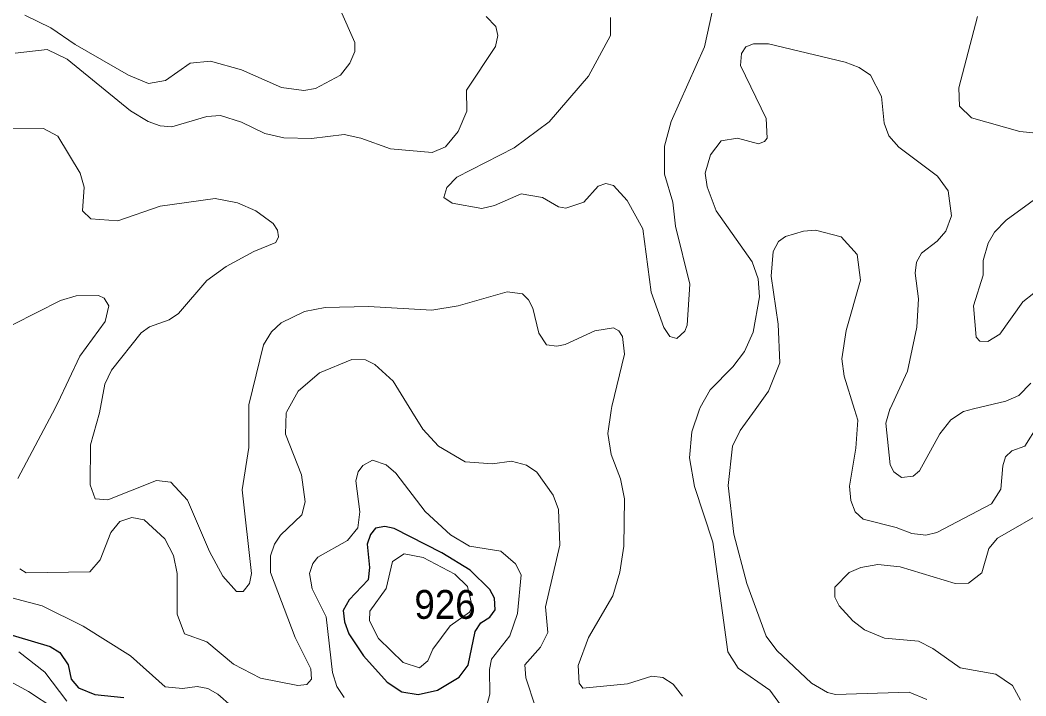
# Model space of a CAD drawing. Extents: x 473.9 to 500, y 7733.1 to 7760.8.
# Drawn here: x 486.475 to 489.264, y 7741.528 to 7743.401 of the extents above; entities that cross this region are included whole.
import ezdxf
from ezdxf.enums import TextEntityAlignment as Align

# ---------------------------------------------------------------- set-up
doc = ezdxf.new("R2010")
doc.units = 0
doc.header["$LTSCALE"] = 0.032
for name, color, linetype, lineweight in [('1', 7, 'Continuous', 25), ('2', 7, 'Continuous', 13), ('26', 7, 'Continuous', 25)]:
    doc.layers.add(name, color=color, linetype=linetype, lineweight=lineweight)
doc.layers.add('21', color=7, linetype='Continuous')

msp = doc.modelspace()

# ---------------------------------------------------------------- linework, layer by layer
at = {"layer": '1'}
msp.add_lwpolyline([(487.7365, 7741.7062), (487.7525, 7741.7297), (487.7769, 7741.7462), (487.7922, 7741.7664), (487.7906, 7741.7985), (487.7773, 7741.8222), (487.7228, 7741.8761), (487.644, 7741.9245), (487.5117, 7741.9919), (487.4865, 7741.9971), (487.4603, 7741.9926), (487.446, 7741.975), (487.4369, 7741.948), (487.4433, 7741.8837), (487.4403, 7741.8491), (487.3868, 7741.7937), (487.371, 7741.7642), (487.374, 7741.7331), (487.3859, 7741.6994), (487.4268, 7741.6389), (487.4924, 7741.5654), (487.5336, 7741.5386), (487.5787, 7741.5316), (487.6324, 7741.5437), (487.6925, 7741.5798), (487.7176, 7741.6125)], close=True, dxfattribs=at)
msp.add_lwpolyline([(486.4182, 7741.706), (486.5584, 7741.6649), (486.5849, 7741.6477), (486.6079, 7741.6135), (486.6161, 7741.5742), (486.6365, 7741.5497), (486.6823, 7741.5313), (486.7627, 7741.5227)], dxfattribs=at)
at = {"layer": '2'}
for points in [[(488.1121, 7743.4086), (488.1123, 7743.3588), (488.0507, 7743.2462), (487.9419, 7743.1195), (487.8444, 7743.0473), (487.6862, 7742.9659), (487.6579, 7742.9375), (487.6494, 7742.9097), (487.6726, 7742.8936), (487.7555, 7742.8791), (487.7899, 7742.887), (487.864, 7742.9198), (487.9233, 7742.9096), (487.9678, 7742.8834), (487.9876, 7742.8799), (488.0377, 7742.8962), (488.0775, 7742.9414), (488.0986, 7742.9481), (488.1206, 7742.9427), (488.1584, 7742.9011), (488.2018, 7742.8223), (488.225, 7742.647), (488.2598, 7742.5488), (488.2763, 7742.5239), (488.2959, 7742.5189), (488.3182, 7742.5385), (488.3244, 7742.5553), (488.3317, 7742.6689), (488.2923, 7742.8298), (488.2844, 7742.8962), (488.2618, 7742.9745), (488.2619, 7743.0517), (488.2801, 7743.1203), (488.3726, 7743.3277), (488.4002, 7743.4537)], [(487.7669, 7743.4116), (487.794, 7743.3834), (487.7996, 7743.3588), (487.7933, 7743.3284), (487.7129, 7743.2072), (487.7133, 7743.1487), (487.6899, 7743.0923), (487.654, 7743.0498), (487.6173, 7743.0343), (487.5015, 7743.0441), (487.4194, 7743.0741), (487.3733, 7743.0841), (487.2828, 7743.0729), (487.2059, 7743.075), (487.1531, 7743.0866), (487.0883, 7743.118), (487.0308, 7743.1371), (486.9927, 7743.134), (486.8957, 7743.1051), (486.8632, 7743.1084), (486.8296, 7743.1203), (486.7809, 7743.1495), (486.6053, 7743.2928), (486.5495, 7743.3196), (486.461, 7743.3094)], [(486.4876, 7743.4152), (486.5597, 7743.3799), (486.6271, 7743.3338), (486.7752, 7743.249), (486.8309, 7743.2255), (486.8778, 7743.2342), (486.9461, 7743.2821), (487.0025, 7743.2875), (487.0888, 7743.2635), (487.1992, 7743.2141), (487.2614, 7743.2064), (487.2935, 7743.2116), (487.3629, 7743.249), (487.3887, 7743.2817), (487.4031, 7743.3148)], [(487.4031, 7743.3148), (487.4029, 7743.3395), (487.363, 7743.4293)], [(489.1293, 7743.4114), (489.0775, 7743.2134), (489.0795, 7743.1627), (489.1131, 7743.1304), (489.2471, 7743.0928), (489.3638, 7743.0802)], [(488.5908, 7741.4925), (488.5536, 7741.5436), (488.4663, 7741.6045), (488.4375, 7741.65), (488.3958, 7741.9534), (488.3452, 7742.1083), (488.3311, 7742.1881), (488.3377, 7742.26), (488.358, 7742.3198), (488.3604, 7742.327), (488.3885, 7742.3761), (488.4508, 7742.4401), (488.4831, 7742.4825), (488.5073, 7742.536), (488.5247, 7742.6341), (488.5212, 7742.6839), (488.5043, 7742.7316), (488.405, 7742.8723), (488.3796, 7742.9391), (488.3744, 7742.9774), (488.3895, 7743.0274), (488.4187, 7743.0663), (488.4636, 7743.0744), (488.5226, 7743.0584), (488.5391, 7743.0644), (488.5458, 7743.0739), (488.5432, 7743.1283), (488.4725, 7743.2752), (488.4749, 7743.3084), (488.4871, 7743.3271), (488.5088, 7743.3359), (488.5504, 7743.3357), (488.7627, 7743.2847), (488.8018, 7743.2703), (488.833, 7743.2484), (488.8632, 7743.1894), (488.8709, 7743.1156), (488.884, 7743.0808), (488.9115, 7743.0489), (489.0187, 7742.9687), (489.0482, 7742.9281), (489.0578, 7742.8587), (489.0414, 7742.8158), (489.018, 7742.7887), (488.9742, 7742.7552), (488.96, 7742.7306), (488.9565, 7742.7), (488.9662, 7742.6284), (488.9615, 7742.5499), (488.9351, 7742.4283), (488.8871, 7742.3238), (488.8866, 7742.3222), (488.8749, 7742.2839), (488.8874, 7742.1683), (488.8971, 7742.1484), (488.9186, 7742.1332), (488.9512, 7742.1373), (488.9689, 7742.152), (489.0252, 7742.254), (489.0552, 7742.2926), (489.0902, 7742.3166), (489.1185, 7742.3233), (489.2081, 7742.3445), (489.2439, 7742.3601), (489.2776, 7742.3947)], [(486.4242, 7743.0997), (486.5394, 7743.101), (486.5798, 7743.08), (486.6416, 7742.9772), (486.6521, 7742.9385), (486.6483, 7742.8728), (486.6709, 7742.85), (486.7457, 7742.845), (486.8631, 7742.8853), (487.0158, 7742.9064), (487.0775, 7742.8943), (487.1289, 7742.8726), (487.1763, 7742.8372), (487.1887, 7742.8186), (487.1916, 7742.8002), (487.1839, 7742.7849), (487.1226, 7742.7601), (487.0458, 7742.7185), (486.9923, 7742.6797), (486.9139, 7742.5876), (486.8882, 7742.5706), (486.8336, 7742.5512), (486.811, 7742.5345), (486.728, 7742.4304), (486.7098, 7742.3924), (486.6954, 7742.3125), (486.6953, 7742.3122), (486.6697, 7742.2236), (486.6691, 7742.1126), (486.6831, 7742.0744), (486.7179, 7742.0708), (486.853, 7742.1246), (486.8927, 7742.1205), (486.9391, 7742.0703), (486.9998, 7741.9282), (487.0371, 7741.8594), (487.0746, 7741.8174), (487.0934, 7741.8173), (487.1105, 7741.8388), (487.1169, 7741.8671), (487.0903, 7742.0986), (487.1088, 7742.2165), (487.1089, 7742.3141), (487.1089, 7742.3345), (487.1493, 7742.5012), (487.1719, 7742.5369), (487.1989, 7742.5624), (487.2635, 7742.5934), (487.3209, 7742.6042), (487.4411, 7742.6074), (487.6167, 7742.597), (487.6895, 7742.6092), (487.8253, 7742.6479), (487.8675, 7742.6424), (487.8846, 7742.6262), (487.8964, 7742.6025), (487.9129, 7742.5338), (487.934, 7742.5009), (487.9635, 7742.4972), (487.9866, 7742.5018), (488.068, 7742.5397), (488.1202, 7742.5486), (488.1352, 7742.5398), (488.145, 7742.5239), (488.1508, 7742.4749), (488.1153, 7742.3302), (488.1136, 7742.3187), (488.1042, 7742.2554), (488.1136, 7742.1967), (488.1395, 7742.1297), (488.1507, 7742.074), (488.1492, 7741.9432), (488.1378, 7741.8703), (488.1186, 7741.8049), (488.0506, 7741.6897), (488.0223, 7741.6114), (488.0254, 7741.5631), (488.0352, 7741.5491), (488.1586, 7741.5607), (488.2262, 7741.5823), (488.2573, 7741.5783), (488.2853, 7741.5598), (488.3116, 7741.5268)], [(489.3379, 7742.9414), (489.2085, 7742.8467), (489.1768, 7742.8138), (489.1593, 7742.7832), (489.1456, 7742.7349), (489.1454, 7742.6943), (489.1184, 7742.6093), (489.1259, 7742.5223), (489.1361, 7742.5115), (489.158, 7742.5107), (489.1913, 7742.5302), (489.2547, 7742.62), (489.3159, 7742.6684)], [(489.297, 7742.2772), (489.2609, 7742.22), (489.2247, 7742.2074), (489.2071, 7742.19), (489.1993, 7742.1651), (489.1944, 7742.1008), (489.1687, 7742.0598), (489.0168, 7741.9805), (488.9862, 7741.973), (488.9471, 7741.9775), (488.9042, 7741.9946), (488.8128, 7742.0175), (488.7907, 7742.0379), (488.7779, 7742.0692), (488.7748, 7742.1088), (488.7918, 7742.2149), (488.7972, 7742.2921), (488.7881, 7742.3218), (488.76, 7742.4138), (488.7531, 7742.4621), (488.765, 7742.5409), (488.8053, 7742.6803), (488.7958, 7742.7515), (488.7514, 7742.8002), (488.6807, 7742.8194), (488.647, 7742.8163), (488.5973, 7742.8011), (488.5775, 7742.7877), (488.5627, 7742.76), (488.5577, 7742.6915), (488.5768, 7742.558), (488.5818, 7742.4514), (488.5504, 7742.3725), (488.5127, 7742.3205), (488.4713, 7742.2635), (488.4497, 7742.2204), (488.4379, 7742.1109), (488.4535, 7741.9758), (488.4902, 7741.8388), (488.5438, 7741.6929), (488.5728, 7741.6531), (488.6689, 7741.5631), (488.7139, 7741.5366), (488.7359, 7741.5311), (488.9396, 7741.5379), (488.9894, 7741.5178)], [(486.4683, 7742.1302), (486.5645, 7742.3116), (486.5795, 7742.3399), (486.6404, 7742.4695), (486.7103, 7742.566), (486.7213, 7742.6093), (486.7084, 7742.6303), (486.6919, 7742.6374), (486.6304, 7742.637), (486.5865, 7742.624), (486.4552, 7742.5577)], [(487.904, 7741.4961), (487.8772, 7741.5776), (487.8742, 7741.6135), (487.9175, 7741.6628), (487.9381, 7741.7036), (487.932, 7741.7749), (487.9716, 7741.9454), (487.9675, 7742.0445), (487.9532, 7742.0842), (487.9076, 7742.1478), (487.8791, 7742.1675), (487.837, 7742.1787), (487.7849, 7742.1709), (487.7089, 7742.1769), (487.6351, 7742.22), (487.5916, 7742.2675), (487.5613, 7742.3162), (487.5088, 7742.4003), (487.4586, 7742.4465), (487.4323, 7742.4598), (487.3943, 7742.4601), (487.3053, 7742.423), (487.2459, 7742.3723), (487.2136, 7742.3146), (487.2122, 7742.312), (487.2105, 7742.2534), (487.2551, 7742.141), (487.2654, 7742.0659), (487.2557, 7742.0294), (487.1965, 7741.9729), (487.18, 7741.9486), (487.169, 7741.9164), (487.1687, 7741.8697), (487.2373, 7741.6897), (487.2807, 7741.6029), (487.2826, 7741.574), (487.2699, 7741.559), (487.2449, 7741.5565), (487.1418, 7741.5766), (487.0661, 7741.6159), (486.9925, 7741.6772), (486.9309, 7741.7), (486.9101, 7741.7545), (486.9101, 7741.867), (486.9, 7741.9169), (486.876, 7741.9634), (486.8186, 7742.0155), (486.7848, 7742.0219), (486.7517, 7742.011), (486.7262, 7741.9802), (486.6973, 7741.9053), (486.668, 7741.8714), (486.4916, 7741.8689), (486.4737, 7741.8796)], [(487.7653, 7741.4872), (487.7776, 7741.5326), (487.7762, 7741.6007), (487.7821, 7741.6293), (487.8324, 7741.694), (487.8537, 7741.7564), (487.8638, 7741.8628), (487.8481, 7741.8939), (487.8079, 7741.9287), (487.7209, 7741.9429), (487.6681, 7741.9738), (487.5981, 7742.0385), (487.5166, 7742.145), (487.4903, 7742.1686), (487.452, 7742.1813), (487.4249, 7742.1666), (487.4118, 7742.1493), (487.4056, 7742.1238), (487.4167, 7742.038), (487.4114, 7741.9935), (487.383, 7741.9585), (487.3007, 7741.9123), (487.2865, 7741.8947), (487.2769, 7741.8671), (487.285, 7741.8244), (487.3235, 7741.747), (487.3414, 7741.5922), (487.3535, 7741.5536), (487.3737, 7741.5233)], [(488.7336, 7741.8295), (488.7732, 7741.8695), (488.8055, 7741.8832), (488.853, 7741.8918), (488.9148, 7741.8858), (489.0677, 7741.8388), (489.1046, 7741.8402), (489.1411, 7741.869), (489.1611, 7741.9361), (489.1845, 7741.9652), (489.3267, 7742.0463)], [(489.2486, 7741.5161), (489.2268, 7741.5567), (489.1806, 7741.5879), (489.0813, 7741.6056), (489.0053, 7741.6594), (488.9663, 7741.6791), (488.8718, 7741.6875), (488.8162, 7741.7106), (488.784, 7741.7353), (488.7459, 7741.7776), (488.7342, 7741.8014), (488.7336, 7741.8295)], [(486.4121, 7741.8095), (486.5362, 7741.777), (486.6495, 7741.721), (486.7812, 7741.6388), (486.8773, 7741.5524), (486.9253, 7741.5484), (486.9655, 7741.554), (486.9956, 7741.5478), (487.0233, 7741.532), (487.0987, 7741.4658)], [(486.604, 7741.5131), (486.5437, 7741.5935), (486.4713, 7741.6498)], [(486.3992, 7741.5931), (486.4986, 7741.5395), (486.6444, 7741.4434), (486.788, 7741.4133)]]:
    msp.add_lwpolyline(points, dxfattribs=at)
msp.add_lwpolyline([(487.6054, 7741.6248), (487.6194, 7741.6567), (487.6676, 7741.7222), (487.7209, 7741.7596), (487.7279, 7741.7765), (487.7158, 7741.831), (487.68, 7741.8655), (487.5926, 7741.9116), (487.5396, 7741.9212), (487.5077, 7741.9), (487.4902, 7741.8258), (487.4448, 7741.7626), (487.4439, 7741.7354), (487.4689, 7741.6869), (487.537, 7741.6205), (487.582, 7741.6056)], close=True, dxfattribs=at)

# ---------------------------------------------------------------- texts
at = {"layer": '21', "width": 0.95}
msp.add_text('926', height=0.08, dxfattribs=at).set_placement((487.5682, 7741.7412))
at = {"layer": '26', "width": 1.15}
msp.add_text('SERRA DOS LOPES OU ÁGUA LIMPA', height=0.12, rotation=327.887, dxfattribs=at).set_placement((486.2932, 7741.203), align=Align.CENTER)

doc.saveas('drawing.dxf')
